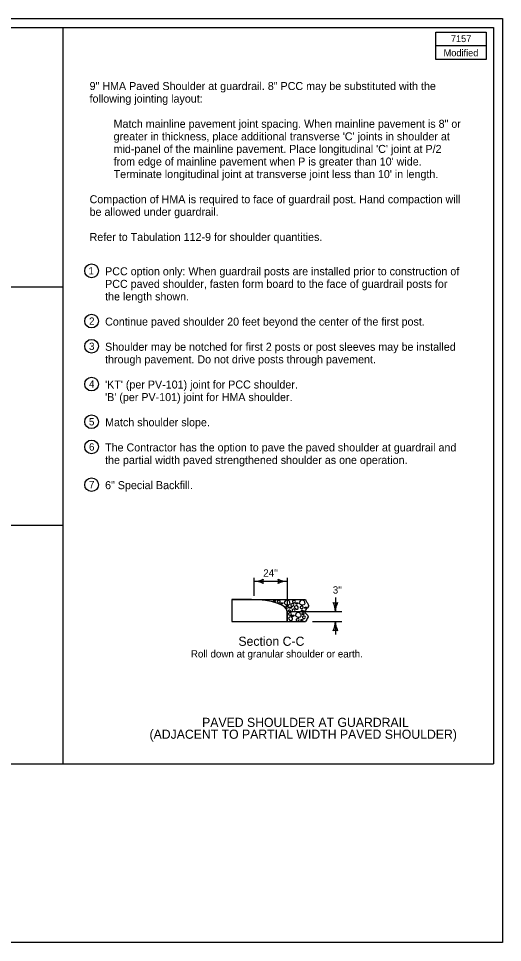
# Model space of a CAD drawing. Extents: x 10133 to 81668, y 5848 to 11018.
# Drawn here: x 12210 to 13268, y 7924 to 9944 of the extents above; entities that cross this region are included whole.
import ezdxf

# ---------------------------------------------------------------- set-up
doc = ezdxf.new("R2010")
doc.units = 0
for name, color, linetype in [('dsnStdDimension', 7, 'Continuous'), ('dsnStdLabel', 7, 'Continuous'), ('dsnStdLineWork', 7, 'Continuous'), ('dsnStdSection', 7, 'Continuous'), ('dsnStdShading', 7, 'Continuous'), ('PlanSheetShape', 7, 'Continuous'), ('SheetBorder', 7, 'Continuous'), ('SheetText', 7, 'Continuous'), ('ShtPlotShape', 7, 'Continuous'), ('ShtPlotShapeBatchPrint', 7, 'Continuous')]:
    doc.layers.add(name, color=color, linetype=linetype)

msp = doc.modelspace()

# ---------------------------------------------------------------- linework, layer by layer
at = {"layer": 'dsnStdDimension'}
for points in [[(12768.9, 8669.4), (12769.8, 8669.2), (12770.3, 8669.2), (12772.7, 8671.6), (12768.7, 8672.4), (12765.2, 8670.3), (12768.1, 8669.6), (12768.9, 8669.4)], [(12775.4, 8669.9), (12775.4, 8670.5), (12775.8, 8670.3), (12780.3, 8673), (12782.7, 8669.8), (12780.6, 8665.7), (12775.5, 8666.8), (12775.3, 8669.3), (12775.4, 8669.9)], [(12784.6, 8663.9), (12785.4, 8663.7), (12785.9, 8663.7), (12788.4, 8666.1), (12784.3, 8666.9), (12780.9, 8664.8), (12783.7, 8664.1), (12784.6, 8663.9)], [(12790.2, 8666.1), (12790, 8666.6), (12790.5, 8666.3), (12792.4, 8672.7), (12800.7, 8673), (12803.4, 8665.7), (12803.6, 8664.9), (12798.8, 8661.2), (12792.1, 8663.3), (12790.5, 8665.7), (12790.2, 8666.1)], [(12808.3, 8669.9), (12808.3, 8670.5), (12808.7, 8670.3), (12813.3, 8673), (12815.7, 8669.8), (12813.5, 8665.7), (12808.4, 8666.8), (12808.3, 8669.3), (12808.3, 8669.9)], [(12817.5, 8663.9), (12818.3, 8663.7), (12818.9, 8663.7), (12821.3, 8666.1), (12817.3, 8666.9), (12813.8, 8664.8), (12816.6, 8664.1), (12817.5, 8663.9)], [(12823.2, 8666.1), (12822.9, 8666.6), (12823.4, 8666.3), (12825.3, 8672.7), (12833.6, 8673), (12836.3, 8665.7), (12836.6, 8664.9), (12831.7, 8661.2), (12825, 8663.3), (12823.4, 8665.7), (12823.2, 8666.1)], [(12793.7, 8658.7), (12793.8, 8659.2), (12794.1, 8659.1), (12798.7, 8661.7), (12801.1, 8658.5), (12799, 8654.5), (12793.9, 8655.6), (12793.7, 8658.1), (12793.7, 8658.7)], [(12799.1, 8649), (12798.7, 8649.5), (12799.1, 8649.8), (12803.4, 8651.2), (12804.7, 8647.7), (12801.5, 8646.9), (12799.5, 8648.5), (12799.1, 8649)], [(12803.9, 8654.7), (12804.7, 8654.5), (12805.2, 8654.5), (12807.6, 8656.9), (12803.6, 8657.7), (12800.1, 8655.6), (12803, 8654.8), (12803.9, 8654.7)], [(12804.8, 8662.7), (12804.8, 8663.3), (12805.2, 8663.1), (12809.7, 8665.8), (12812.1, 8662.6), (12810, 8658.6), (12804.9, 8659.7), (12804.7, 8662.2), (12804.8, 8662.7)], [(12807.6, 8650.9), (12807.7, 8651.5), (12808, 8651.3), (12812.6, 8654), (12815, 8650.8), (12812.8, 8646.8), (12807.8, 8647.8), (12807.6, 8650.3), (12807.6, 8650.9)], [(12812.8, 8656.7), (12812.3, 8657.9), (12812.4, 8658.2), (12817, 8661.2), (12821, 8659.3), (12822.1, 8654), (12815.9, 8651.3), (12813.4, 8655.6), (12812.8, 8656.7)], [(12814.7, 8639), (12814.5, 8639.5), (12815, 8639.2), (12816.9, 8645.6), (12825.2, 8645.8), (12827.9, 8638.6), (12828.1, 8637.8), (12823.3, 8634.1), (12816.6, 8636.2), (12815, 8638.5), (12814.7, 8639)], [(12825, 8657.3), (12825.1, 8657.9), (12825.4, 8657.7), (12830, 8660.4), (12832.4, 8657.2), (12830.3, 8653.2), (12825.2, 8654.3), (12825, 8656.8), (12825, 8657.3)], [(12827.8, 8648.6), (12827.4, 8649), (12827.7, 8649.4), (12832, 8650.7), (12833.3, 8647.3), (12830.1, 8646.5), (12828.2, 8648.1), (12827.8, 8648.6)], [(12836.8, 8654.7), (12837.6, 8654.5), (12838.2, 8654.5), (12840.6, 8656.9), (12836.6, 8657.7), (12833.1, 8655.6), (12835.9, 8654.8), (12836.8, 8654.7)], [(12800.3, 8632.2), (12799.7, 8633.4), (12799.9, 8633.7), (12804.4, 8636.7), (12808.5, 8634.8), (12809.5, 8629.4), (12803.4, 8626.8), (12800.9, 8631), (12800.3, 8632.2)], [(12799.9, 8642.8), (12799.9, 8643.3), (12800.3, 8643.2), (12804.8, 8645.8), (12807.2, 8642.6), (12805.1, 8638.6), (12800, 8639.7), (12799.8, 8642.2), (12799.9, 8642.8)], [(12809.1, 8636.8), (12809.9, 8636.6), (12810.5, 8636.6), (12812.9, 8639), (12808.9, 8639.8), (12805.4, 8637.7), (12808.2, 8637), (12809.1, 8636.8)], [(12816.6, 8630.2), (12816.7, 8630.8), (12817, 8630.6), (12821.6, 8633.3), (12824, 8630.1), (12821.8, 8626.1), (12816.8, 8627.1), (12816.6, 8629.6), (12816.6, 8630.2)], [(12828.4, 8627.5), (12829.2, 8627.4), (12829.7, 8627.4), (12832.2, 8629.8), (12828.1, 8630.6), (12824.7, 8628.4), (12827.5, 8627.7), (12828.4, 8627.5)], [(12829.1, 8642.5), (12828.7, 8643), (12829, 8643.3), (12833.3, 8644.7), (12834.6, 8641.2), (12831.4, 8640.4), (12829.5, 8642), (12829.1, 8642.5)], [(12830.2, 8635.6), (12830.2, 8636.2), (12830.6, 8636), (12835.2, 8638.7), (12837.6, 8635.5), (12835.4, 8631.5), (12830.3, 8632.6), (12830.2, 8635.1), (12830.2, 8635.6)]]:
    msp.add_open_spline(points, degree=3, dxfattribs=at)
at = {"layer": 'dsnStdLabel'}
for centre in [(12369.6, 9392.4), (12369.6, 9282.4), (12369.6, 9227.4), (12369.6, 9144.9), (12369.6, 9062.4), (12369.6, 9007.4), (12369.6, 8924.9)]:
    msp.add_circle(centre, 15, dxfattribs=at)
at = {"layer": 'dsnStdLineWork'}
for p, q in [((13247.9, 9924.4), (13247.9, 9924.4)), ((12676.2, 8673.7), (12676.2, 8625.7)), ((12676.2, 8673.7), (12719.3, 8673.6)), ((12719.3, 8673.6), (12837, 8673.6)), ((12797.2, 8647.5), (12797.2, 8625.7)), ((12676.2, 8625.7), (12797.2, 8625.7)), ((12797.2, 8625.7), (12837, 8625.7))]:
    msp.add_line(p, q, dxfattribs=at)
msp.add_ellipse((12719.3, 8647.5), major_axis=(77.9, 0), ratio=0.335273, start_param=0, end_param=1.570796, dxfattribs=at)
msp.add_spline([(12837, 8673.6), (12838.4, 8670.4), (12840.3, 8667.3), (12842.2, 8664.2), (12843.6, 8661.1), (12843.7, 8659.4), (12843, 8657.6), (12840.2, 8654.2), (12837, 8650.7), (12835.9, 8648.9), (12835.6, 8648), (12835.5, 8647.2), (12835.5, 8646.8), (12835.8, 8645.6), (12836.8, 8644), (12839.8, 8640.8), (12842.3, 8637.6), (12842.7, 8636), (12842.6, 8635.3), (12842.5, 8634.9), (12842.3, 8634.5), (12837, 8625.7)], degree=3, dxfattribs=at)
at = {"layer": 'dsnStdShading'}
for p, q in [((12307.8, 8314.4), (12307.8, 9924.4)), ((12307.8, 9356.4), (10152.2, 9356.4)), ((12307.8, 8835.4), (10152.2, 8835.4))]:
    msp.add_line(p, q, dxfattribs=at)
at = {"layer": 'PlanSheetShape'}
for p, q in [((12719.3, 8673.7), (12676.2, 8673.7)), ((12676.2, 8673.7), (12676.2, 8625.7)), ((12797.2, 8625.7), (12797.2, 8647.5)), ((12676.2, 8625.7), (12797.2, 8625.7))]:
    msp.add_line(p, q, dxfattribs=at)
msp.add_lwpolyline([(12719.3, 8673.6), (12719.3, 8673.7)], dxfattribs=at)
msp.add_ellipse((12719.3, 8647.5), major_axis=(77.9, 0), ratio=0.335273, start_param=0, end_param=1.570796, dxfattribs=at)
at = {"layer": 'SheetBorder'}
msp.add_lwpolyline([(10132.5, 9944), (13267.5, 9944), (13267.5, 7924), (10132.5, 7924)], close=True, dxfattribs=at)
at = {"layer": 'SheetText'}
msp.add_lwpolyline([(13232.1, 9914.4), (13232.1, 9854.4), (13122.1, 9854.4), (13122.1, 9914.4), (13232.1, 9914.4), (13232.1, 9884.4), (13122.1, 9884.4)], dxfattribs=at)
at = {"layer": 'ShtPlotShape'}
for p, q in [((12724.6, 8682.2), (12724.6, 8721.5)), ((12724.6, 8713.6), (12797.2, 8713.6)), ((12797.2, 8721.5), (12797.2, 8658)), ((12902.3, 8678.4), (12902.3, 8647.5)), ((12804, 8647.5), (12916.1, 8647.5)), ((12852, 8625.7), (12916.1, 8625.7)), ((12902.3, 8625.7), (12902.3, 8597.1))]:
    msp.add_line(p, q, dxfattribs=at)
for centre, radius, start, end in [((12724.6, 8756.1), 42.5, 270, 298.0725), ((12724.6, 8671.1), 42.5, 61.9275, 90), ((12760.3, 8713.6), 16.4, 162.2666, 197.7334), ((12761.5, 8713.6), 16.4, 342.2666, 17.7334), ((12797.2, 8756.1), 42.5, 241.9275, 270), ((12797.2, 8671.1), 42.5, 90, 118.0725), ((12902.3, 8683.1), 16.4, 252.2666, 287.7334), ((12859.8, 8647.5), 42.5, 0, 28.0725), ((12944.8, 8647.5), 42.5, 151.9275, 180), ((12859.8, 8625.7), 42.5, 331.9275, 360), ((12944.8, 8625.7), 42.5, 180, 208.0725), ((12902.3, 8590), 16.4, 72.2666, 107.7334)]:
    msp.add_arc(centre, radius, start, end, dxfattribs=at)
at = {"layer": 'ShtPlotShapeBatchPrint'}
for p, q in [((10152.2, 9924.4), (13247.9, 9924.4)), ((13247.9, 9924.4), (13247.9, 8314.4)), ((10152.2, 8314.4), (13247.9, 8314.4))]:
    msp.add_line(p, q, dxfattribs=at)

# ---------------------------------------------------------------- texts
at = {"layer": 'dsnStdLabel'}
for s, height, p in [('9" HMA Paved Shoulder at guardrail. 8" PCC may be substituted with the', 17.5, (12365.2, 9787.6)), ('following jointing layout:', 17.5, (12365.2, 9760.1)), ('Match mainline pavement joint spacing. When mainline pavement is 8" or ', 17.5, (12417.7, 9705.1)), ("greater in thickness, place additional transverse 'C' joints in shoulder at ", 17.5, (12417.7, 9677.6)), ("mid-panel of the mainline pavement. Place longitudinal 'C' joint at P/2 ", 17.5, (12417.7, 9650.1)), ("from edge of mainline pavement when P is greater than 10' wide. ", 17.5, (12417.7, 9622.6)), ("Terminate longitudinal joint at transverse joint less than 10' in length.", 17.5, (12417.7, 9595.1)), ('Compaction of HMA is required to face of guardrail post. Hand compaction will ', 17.5, (12365.2, 9540.1)), ('be allowed under guardrail. ', 17.5, (12365.2, 9512.6)), ('Refer to Tabulation 112-9 for shoulder quantities.', 17.5, (12365.2, 9457.6)), ('1', 16, (12362.8, 9384.4)), ('PCC option only: When guardrail posts are installed prior to construction of ', 17.5, (12399.1, 9382.6)), ('PCC paved shoulder, fasten form board to the face of guardrail posts for ', 17.5, (12399.1, 9355.1)), ('the length shown.', 17.5, (12399.1, 9327.6)), ('2', 16, (12364, 9274.4)), ('Continue paved shoulder 20 feet beyond the center of the first post.', 17.5, (12399.1, 9272.6)), ('3', 16, (12363.9, 9219.4)), ('Shoulder may be notched for first 2 posts or post sleeves may be installed ', 17.5, (12399.1, 9217.6)), ('through pavement. Do not drive posts through pavement.', 17.5, (12399.1, 9190.1)), ('4', 16, (12363.9, 9136.9)), ("'KT' (per PV-101) joint for PCC shoulder.", 17.5, (12399.1, 9135.1)), ("'B' (per PV-101) joint for HMA shoulder.", 17.5, (12399.1, 9107.6)), ('5', 16, (12363.8, 9054.4)), ('Match shoulder slope.', 17.5, (12399.1, 9052.6)), ('6', 16, (12363.9, 8999.4)), ('The Contractor has the option to pave the paved shoulder at guardrail and ', 17.5, (12399.1, 8997.6)), ('the partial width paved strengthened shoulder as one operation.', 17.5, (12399.1, 8970.1)), ('7', 16, (12363.9, 8916.9)), ('6" Special Backfill.', 17.5, (12399.1, 8915.1))]:
    msp.add_text(s, height=height, dxfattribs=at).set_placement(p)
at = {"layer": 'dsnStdSection'}
for s, height, p in [('Section C-C', 20, (12690.4, 8572.6)), ('Roll down at granular shoulder or earth.', 16, (12586.5, 8547.1)), ('PAVED SHOULDER AT GUARDRAIL', 20, (12611.1, 8395.3)), ('(ADJACENT TO PARTIAL WIDTH PAVED SHOULDER)', 20, (12496.2, 8369.4))]:
    msp.add_text(s, height=height, dxfattribs=at).set_placement(p)
at = {"layer": 'SheetText'}
for s, p in [('7157', (13154.7, 9892.4)), ('Modified', (13138.9, 9861.4))]:
    msp.add_text(s, height=15, dxfattribs=at).set_placement(p)
at = {"layer": 'ShtPlotShape'}
for s, p in [("24''", (12744.7, 8723.8)), ("3'' ", (12896.6, 8686.8))]:
    msp.add_text(s, height=16, dxfattribs=at).set_placement(p)

doc.saveas('drawing.dxf')
